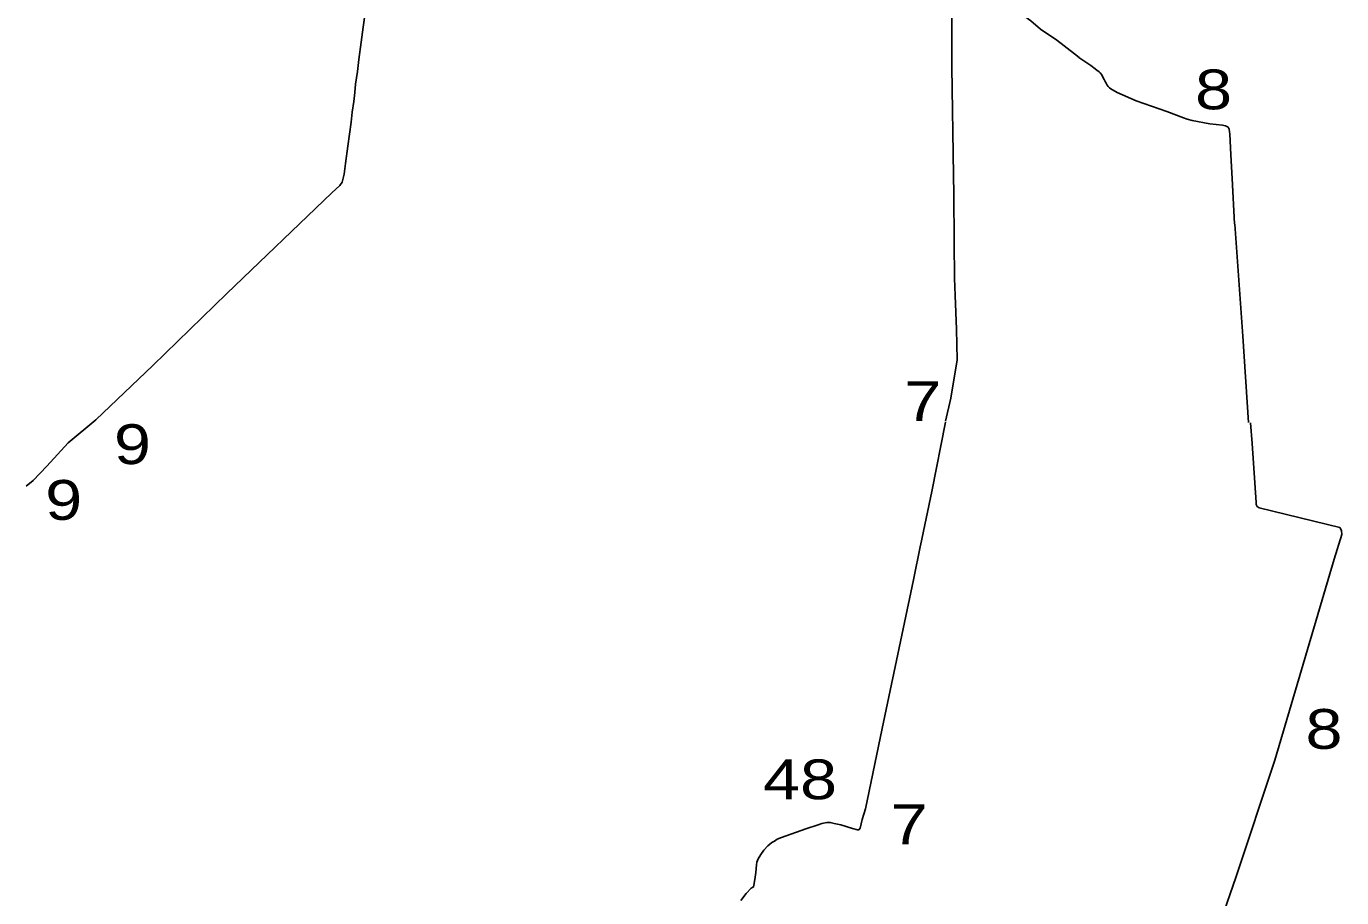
# Model space of a CAD drawing. Extents: x 476989 to 498418, y 4381813 to 4416555.
# Drawn here: x 485779 to 487432, y 4383532 to 4384627 of the extents above; entities that cross this region are included whole.
import ezdxf
from ezdxf.enums import TextEntityAlignment as Align

# ---------------------------------------------------------------- set-up
doc = ezdxf.new("R2010")
doc.units = 0
doc.header["$LTSCALE"] = 20
doc.layers.add('13', color=7, linetype='Continuous', lineweight=13)
doc.layers.add('6', color=7, linetype='Continuous', lineweight=25)

msp = doc.modelspace()

# ---------------------------------------------------------------- linework, layer by layer
at = {"layer": '6'}
for p, q in [((487294.23, 4384435.36), (487297.15, 4384378.58)), ((485866.75, 4384132.44), (485938.06, 4384200.82)), ((486902.72, 4383974.83), (486893.73, 4383931.56))]:
    msp.add_line(p, q, dxfattribs=at)
for points in [[(486218.38, 4384758.97), (486215.66, 4384730.87), (486211.01, 4384695.06), (486207.54, 4384662.09), (486202.36, 4384625.46), (486200.14, 4384606.58), (486197.13, 4384584.8), (486195.49, 4384569.88), (486192.94, 4384553.94), (486192.12, 4384543.7), (486190.9, 4384532.35), (486188.75, 4384518.64), (486187.3, 4384506.44), (486183.04, 4384476.01), (486180.3, 4384454.17)], [(486945.56, 4384310.48), (486944.94, 4384355.68), (486944.63, 4384415.82), (486944.32, 4384439.71), (486942.16, 4384575.23), (486941.95, 4384690.43)], [(486942.08, 4384690.84), (486954.99, 4384685.27), (486964.75, 4384681.01), (486968.71, 4384679.29), (486972.07, 4384677.74), (486975.6, 4384676.25), (486980.04, 4384673.88), (486984.28, 4384670.81), (486999.05, 4384662.28), (487012.48, 4384653.89), (487024.7, 4384645.52), (487041.38, 4384633.38), (487053.31, 4384623.24), (487073.79, 4384609.31), (487096.07, 4384592.1), (487101.96, 4384587.52)], [(487101.8, 4384587.52), (487116.55, 4384577.26), (487122.3, 4384573.1), (487124.64, 4384571.25), (487125.02, 4384570.92), (487125.52, 4384570.61), (487127.05, 4384569.38), (487128.24, 4384568.15), (487130.32, 4384565.69), (487131.92, 4384562.86), (487133.39, 4384560.05), (487135.2, 4384556.68), (487136.02, 4384555.28), (487137.14, 4384552.89), (487137.22, 4384552.72), (487138.44, 4384551.25), (487140.08, 4384549.42), (487141.78, 4384547.95), (487149.75, 4384543.71), (487173.68, 4384533.05), (487212.25, 4384519.67), (487233.09, 4384511.72), (487237.67, 4384509.96), (487243.84, 4384508.31), (487266.13, 4384504.33), (487282.11, 4384502.38), (487283.68, 4384502.03), (487285.79, 4384501.45), (487287.55, 4384500.79), (487289.12, 4384499.93), (487290.33, 4384497.55), (487290.92, 4384494.24), (487291.11, 4384491.51), (487292.47, 4384465.24), (487294.23, 4384435.67)], [(485938.1, 4384200.87), (486031.09, 4384290.93), (486163.16, 4384417.62), (486173.25, 4384426.84), (486175.9, 4384430.9), (486178.46, 4384441.13), (486180.3, 4384454.17)], [(487297.44, 4384378.01), (487307.43, 4384237.38), (487314.66, 4384129.23)], [(486934.14, 4384130.55), (486940.93, 4384159.51), (486948.64, 4384207.59), (486948.03, 4384246.42), (486946.18, 4384288.58), (486945.56, 4384310.48)], [(485779.25, 4384049.24), (485787.67, 4384056.24), (485804.97, 4384074.17), (485831.97, 4384103.43), (485866.54, 4384132.39)], [(486934.14, 4384129.53), (486916.73, 4384042.26), (486902.62, 4383974.52)], [(487317.13, 4384128.79), (487319.18, 4384102.5), (487324.43, 4384028.76), (487324.46, 4384025.91), (487325.54, 4384023.43), (487328.03, 4384021.89), (487429.49, 4383997.14), (487431.73, 4383993.45), (487431.84, 4383988.48), (487422.32, 4383957.52), (487348.01, 4383704.94), (487298.99, 4383557.78), (487262.98, 4383453.83)], [(486893.84, 4383931.34), (486880.94, 4383870.04), (486854.54, 4383744.96), (486833.62, 4383644.09)], [(486833.62, 4383644.09), (486829.57, 4383630.55), (486827.02, 4383619.53)], [(486826.89, 4383619.48), (486825.23, 4383617.64), (486823.45, 4383617.32), (486817.23, 4383619.19), (486802.39, 4383623.82), (486794.27, 4383625.68), (486789.22, 4383626.87), (486786.8, 4383626.58), (486784.88, 4383626.6), (486778.78, 4383625.44), (486774.01, 4383623.98), (486758.45, 4383618.79), (486728.02, 4383607.73), (486722.8, 4383605.72), (486719.23, 4383603.45), (486715.99, 4383601.58), (486710.95, 4383597.61), (486705.68, 4383591.8), (486702.17, 4383586.52), (486698.61, 4383581.29), (486697.25, 4383576.87), (486696.73, 4383573.56), (486695.83, 4383564.12), (486694.52, 4383555.26), (486693.37, 4383548.23), (486692.99, 4383545.88), (486689.77, 4383544.13), (486683.85, 4383537.38), (486677.07, 4383528.72)]]:
    msp.add_lwpolyline(points, dxfattribs=at)

# ---------------------------------------------------------------- texts
at = {"layer": '13', "width": 1.25}
for s, p in [('8', (487270.88, 4384522.38)), ('7', (486905.66, 4384130.97))]:
    msp.add_text(s, height=50, dxfattribs=at).set_placement(p, align=Align.CENTER)
for s, p in [('9', (485889.36, 4384076.87)), ('9', (485802.95, 4384006.85)), ('8', (487386.35, 4383719.24)), ('48', (486704.87, 4383655.94)), ('7', (486865.07, 4383599.48))]:
    msp.add_text(s, height=50, dxfattribs=at).set_placement(p)

doc.saveas('drawing.dxf')
